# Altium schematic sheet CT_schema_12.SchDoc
size 145 x 119 mm
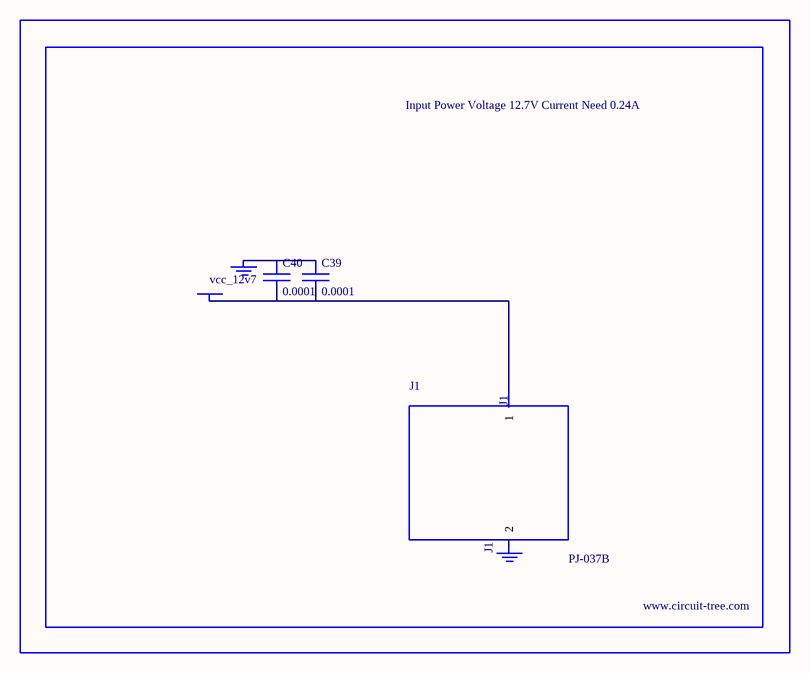
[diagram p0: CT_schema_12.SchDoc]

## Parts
BORDER11  (no value)
C39  0.0001  [EXV-9H]
C40  0.0001  [EXV-9H]
GND_INSTANCE_11_0  (no value)
GND_INSTANCE_11_1  (no value)
J1  PJ-037B  [PJ-037B_PACKAGE]
POWER_INSTANCE_11_0  vcc_12v7

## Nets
NetC39_1: C39.1 C40.1 GND_INSTANCE_11_0.0(GND)
NetC39_2: C39.2 C40.2 J1.1 POWER_INSTANCE_11_0.0(PWR)

Not connected (* = marked no-connect by the designer): GND_INSTANCE_11_1 0(GND); J1 2

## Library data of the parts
BORDER11 = BORDER_PAGE11
C39 C40 = EDK107M035A9HAA
GND_INSTANCE_11_0 GND_INSTANCE_11_1 = GND
POWER_INSTANCE_11_0 = PWR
